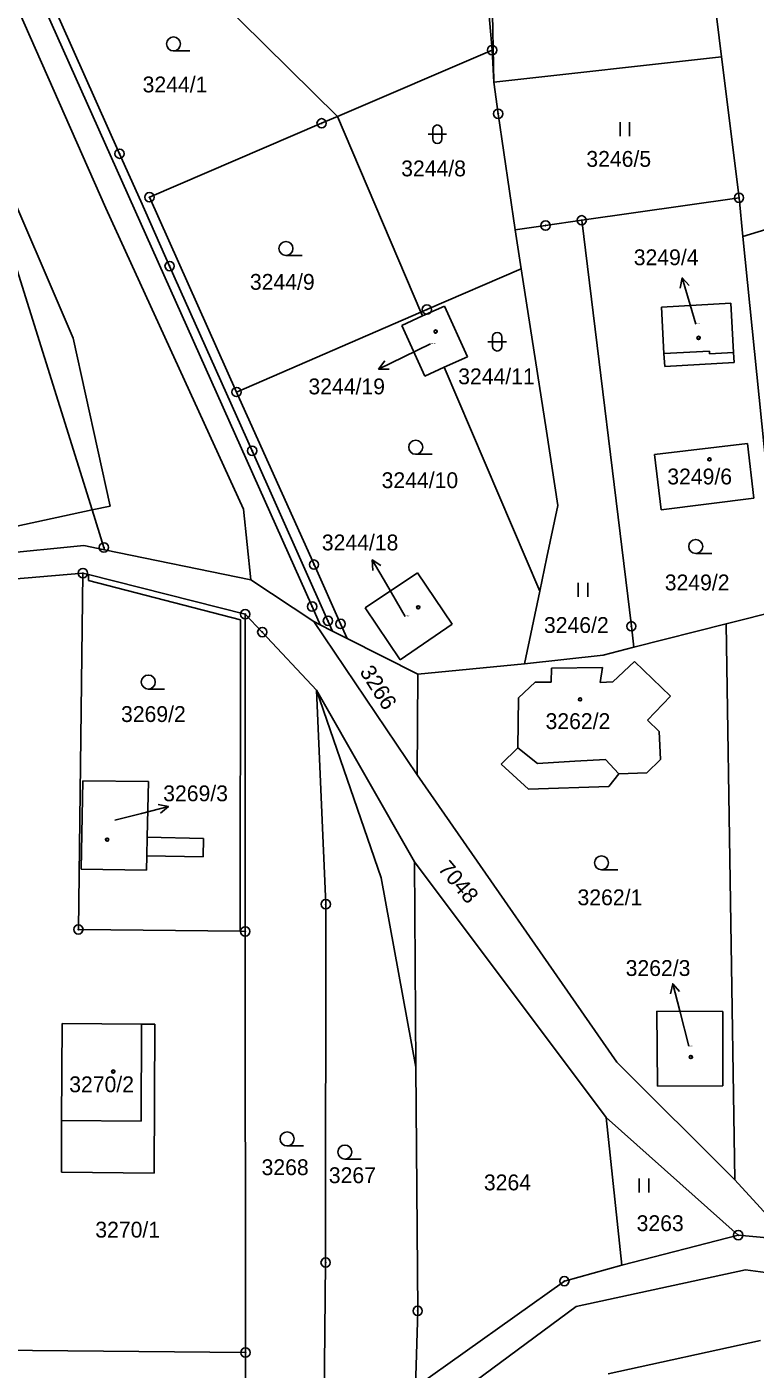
# Model space of a CAD drawing. Extents: x -593183 to -588034, y -1130415 to -1124994.
# Drawn here: x -592537.4 to -592459.2, y -1128135.2 to -1127991.1 of the extents above; entities that cross this region are included whole.
import ezdxf

# ---------------------------------------------------------------- set-up
doc = ezdxf.new("R2010")
doc.units = 0
for name, color, linetype in [('Vrstva 1', 7, 'Continuous'), ('Vrstva 16', 7, 'Continuous'), ('Vrstva 18', 7, 'Continuous'), ('Vrstva 19', 7, 'Continuous'), ('Vrstva 24', 7, 'Continuous'), ('Vrstva 25', 7, 'Continuous'), ('Vrstva 4', 7, 'Continuous')]:
    doc.layers.add(name, color=color, linetype=linetype)

msp = doc.modelspace()

# ---------------------------------------------------------------- linework, layer by layer
at = {"layer": 'Vrstva 1'}
for p, q in [((-592487.85, -1127966.57), (-592487.23, -1127997.07)), ((-592529.53, -1127975.52), (-592504.02, -1128000.74)), ((-592543.23, -1127978.11), (-592528.89, -1128010.56)), ((-592464.13, -1127983.42), (-592462.78, -1127994.34)), ((-592536.01, -1127987.86), (-592506.75, -1128053.34)), ((-592535.34, -1127986.99), (-592527.42, -1128004.73)), ((-592504.02, -1128000.74), (-592487.42, -1127993.61)), ((-592487.42, -1127993.61), (-592487.23, -1127997.07)), ((-592487.23, -1127997.07), (-592462.78, -1127994.34)), ((-592462.78, -1127994.34), (-592460.91, -1128009.46)), ((-592487.23, -1127997.07), (-592486.77, -1128000.44)), ((-592505.72, -1128001.47), (-592504.02, -1128000.74)), ((-592504.02, -1128000.74), (-592495.07, -1128021.74)), ((-592486.77, -1128000.44), (-592484.94, -1128012.91)), ((-592524.21, -1128009.41), (-592505.72, -1128001.47)), ((-592527.42, -1128004.73), (-592525.15, -1128009.81)), ((-592542, -1128005.81), (-592530.36, -1128042.97)), ((-592525.15, -1128009.81), (-592522.04, -1128016.79)), ((-592524.21, -1128009.41), (-592514.85, -1128030.31)), ((-592460.91, -1128009.46), (-592477.8, -1128011.88)), ((-592460.91, -1128009.46), (-592460.49, -1128013.61)), ((-592460.49, -1128013.61), (-592447.19, -1128009.56)), ((-592528.89, -1128010.56), (-592514.12, -1128042.89)), ((-592484.94, -1128012.91), (-592481.68, -1128012.44)), ((-592477.8, -1128011.88), (-592481.68, -1128012.44)), ((-592477.8, -1128011.88), (-592472.47, -1128055.46)), ((-592484.94, -1128012.91), (-592484.29, -1128017.08)), ((-592460.49, -1128013.61), (-592456.72, -1128050.99)), ((-592522.04, -1128016.79), (-592513.18, -1128036.62)), ((-592494.42, -1128021.46), (-592484.29, -1128017.08)), ((-592484.29, -1128017.08), (-592481.59, -1128034.52)), ((-592495.07, -1128021.74), (-592494.42, -1128021.46)), ((-592494.89, -1128022.15), (-592492.54, -1128021.08)), ((-592492.54, -1128021.08), (-592490.06, -1128026.52)), ((-592469.24, -1128021.2), (-592461.78, -1128020.79)), ((-592468.97, -1128026.18), (-592469.24, -1128021.2)), ((-592461.78, -1128020.79), (-592461.49, -1128026.07)), ((-592514.85, -1128030.31), (-592495.07, -1128021.74)), ((-592497.12, -1128023.17), (-592494.89, -1128022.15)), ((-592494.89, -1128022.15), (-592495.07, -1128021.74)), ((-592497.12, -1128023.17), (-592494.64, -1128028.61)), ((-592490.06, -1128026.52), (-592492.55, -1128027.66)), ((-592468.89, -1128027.57), (-592468.97, -1128026.18)), ((-592461.43, -1128027.16), (-592468.89, -1128027.57)), ((-592461.49, -1128026.07), (-592461.43, -1128027.16)), ((-592494.64, -1128028.61), (-592492.55, -1128027.66)), ((-592492.55, -1128027.66), (-592482.3, -1128051.69)), ((-592514.85, -1128030.31), (-592506.54, -1128048.84)), ((-592481.59, -1128034.52), (-592480.36, -1128042.49)), ((-592460.01, -1128035.84), (-592469.98, -1128037.03)), ((-592459.33, -1128041.72), (-592460.01, -1128035.84)), ((-592513.18, -1128036.62), (-592505.04, -1128054.86)), ((-592469.98, -1128037.03), (-592469.28, -1128042.94)), ((-592530.36, -1128042.97), (-592529.1, -1128046.99)), ((-592513.31, -1128050.47), (-592514.12, -1128042.89)), ((-592480.36, -1128042.49), (-592481.54, -1128048.05)), ((-592469.28, -1128042.94), (-592459.33, -1128041.72)), ((-592543.51, -1128048), (-592531.26, -1128046.8)), ((-592531.26, -1128046.8), (-592529.02, -1128047.26)), ((-592529.1, -1128046.99), (-592529.02, -1128047.26)), ((-592529.02, -1128047.26), (-592513.31, -1128050.47)), ((-592506.54, -1128048.84), (-592503.69, -1128055.2)), ((-592481.54, -1128048.05), (-592482.3, -1128051.69)), ((-592543.15, -1128050.75), (-592531.35, -1128049.75)), ((-592531.35, -1128049.75), (-592531.84, -1128088)), ((-592531.35, -1128049.75), (-592530.74, -1128049.9)), ((-592530.74, -1128049.9), (-592513.93, -1128054.16)), ((-592501.03, -1128053.49), (-592495.42, -1128049.71)), ((-592495.42, -1128049.71), (-592491.69, -1128055.24)), ((-592513.31, -1128050.47), (-592506.57, -1128054.94)), ((-592483.95, -1128059.48), (-592482.3, -1128051.69)), ((-592513.93, -1128054.16), (-592512.09, -1128056.08)), ((-592513.93, -1128054.16), (-592513.92, -1128088.21)), ((-592506.75, -1128053.34), (-592505.87, -1128055.3)), ((-592497.29, -1128059.06), (-592501.03, -1128053.49)), ((-592462.3, -1128055.18), (-592456.44, -1128053.72)), ((-592512.09, -1128056.08), (-592506.27, -1128062.3)), ((-592505.87, -1128055.3), (-592506.57, -1128054.94)), ((-592506.57, -1128054.94), (-592495.45, -1128071.4)), ((-592504.54, -1128055.97), (-592505.87, -1128055.3)), ((-592505.04, -1128054.86), (-592504.54, -1128055.97)), ((-592502.99, -1128056.76), (-592504.54, -1128055.97)), ((-592503.69, -1128055.2), (-592502.99, -1128056.76)), ((-592491.69, -1128055.24), (-592497.29, -1128059.06)), ((-592472.47, -1128055.46), (-592472.2, -1128057.7)), ((-592472.2, -1128057.7), (-592462.3, -1128055.18)), ((-592462.3, -1128055.18), (-592461.37, -1128114.86)), ((-592502.99, -1128056.76), (-592495.41, -1128060.61)), ((-592483.95, -1128059.48), (-592475.48, -1128058.54)), ((-592475.48, -1128058.54), (-592472.2, -1128057.7)), ((-592495.41, -1128060.61), (-592483.95, -1128059.48)), ((-592481.03, -1128059.97), (-592481.06, -1128061.44)), ((-592475.55, -1128059.89), (-592481.03, -1128059.97)), ((-592475.83, -1128061.49), (-592475.55, -1128059.89)), ((-592472.12, -1128059.23), (-592474.45, -1128061.41)), ((-592468.28, -1128062.97), (-592472.12, -1128059.23)), ((-592495.41, -1128060.61), (-592495.45, -1128071.4)), ((-592482.8, -1128061.45), (-592484.58, -1128063.15)), ((-592481.06, -1128061.44), (-592482.8, -1128061.45)), ((-592474.45, -1128061.41), (-592475.83, -1128061.49)), ((-592506.27, -1128062.3), (-592505.28, -1128085.29)), ((-592506.27, -1128062.3), (-592495.76, -1128080.73)), ((-592484.58, -1128063.15), (-592484.66, -1128068.5)), ((-592470.72, -1128065.52), (-592468.28, -1128062.97)), ((-592469.47, -1128066.75), (-592470.72, -1128065.52)), ((-592469.34, -1128069.74), (-592469.47, -1128066.75)), ((-592484.66, -1128068.5), (-592486.43, -1128070.26)), ((-592486.43, -1128070.26), (-592483.51, -1128072.94)), ((-592470.8, -1128071.2), (-592469.34, -1128069.74)), ((-592495.45, -1128071.4), (-592474.03, -1128102.24)), ((-592474.87, -1128072.66), (-592473.8, -1128071.29)), ((-592473.8, -1128071.29), (-592470.8, -1128071.2)), ((-592531.36, -1128072.04), (-592531.54, -1128081.52)), ((-592531.36, -1128072.04), (-592524.32, -1128072.1)), ((-592524.32, -1128072.1), (-592524.45, -1128078.11)), ((-592483.51, -1128072.94), (-592474.87, -1128072.66)), ((-592524.45, -1128078.11), (-592518.4, -1128078.24)), ((-592518.4, -1128078.24), (-592518.44, -1128080.21)), ((-592524.53, -1128081.64), (-592524.5, -1128080.08)), ((-592518.44, -1128080.21), (-592524.5, -1128080.08)), ((-592531.54, -1128081.52), (-592524.53, -1128081.64)), ((-592495.76, -1128080.73), (-592495.6, -1128102.77)), ((-592495.76, -1128080.73), (-592475.19, -1128108.18)), ((-592505.28, -1128085.29), (-592505.29, -1128123.75)), ((-592531.84, -1128088), (-592514.46, -1128088.2)), ((-592514.46, -1128088.2), (-592513.92, -1128088.21)), ((-592513.92, -1128088.21), (-592513.9, -1128133.42)), ((-592469.72, -1128096.78), (-592462.66, -1128096.82)), ((-592469.66, -1128104.82), (-592469.72, -1128096.78)), ((-592462.66, -1128096.82), (-592462.63, -1128104.77)), ((-592533.65, -1128108.52), (-592533.59, -1128098.1)), ((-592525.07, -1128098.15), (-592533.59, -1128098.1)), ((-592523.62, -1128098.16), (-592525.07, -1128098.15)), ((-592523.62, -1128098.16), (-592523.7, -1128114.15)), ((-592495.6, -1128102.77), (-592495.41, -1128128.94)), ((-592474.03, -1128102.24), (-592461.37, -1128114.86)), ((-592462.63, -1128104.77), (-592469.66, -1128104.82)), ((-592533.65, -1128114.06), (-592533.65, -1128108.52)), ((-592460.99, -1128120.81), (-592475.19, -1128108.18)), ((-592475.19, -1128108.18), (-592473.48, -1128124.05)), ((-592523.7, -1128114.15), (-592533.65, -1128114.06)), ((-592461.37, -1128114.86), (-592455.46, -1128121.34)), ((-592473.48, -1128124.05), (-592460.99, -1128120.81)), ((-592460.99, -1128120.81), (-592455.46, -1128121.34)), ((-592505.29, -1128123.75), (-592505.61, -1128151.43)), ((-592479.66, -1128125.75), (-592473.48, -1128124.05)), ((-592495.65, -1128137.14), (-592479.66, -1128125.75)), ((-592495.65, -1128137.14), (-592495.41, -1128128.94)), ((-592543.95, -1128133.13), (-592513.9, -1128133.42)), ((-592513.9, -1128133.42), (-592513.89, -1128164.22))]:
    msp.add_line(p, q, dxfattribs=at)
at = {"layer": 'Vrstva 16'}
for p, q in [((-592465.56, -1128023.02), (-592466.17, -1128020.95)), ((-592494.02, -1128025.14), (-592496.9, -1128026.54)), ((-592496.75, -1128054.39), (-592498.77, -1128050.93)), ((-592527.91, -1128076.28), (-592525.07, -1128075.55)), ((-592466.3, -1128100.53), (-592467.28, -1128096.73))]:
    msp.add_line(p, q, dxfattribs=at)
at = {"layer": 'Vrstva 24'}
for centre, radius in [((-592487.42, -1127993.61), 0.5), ((-592487.42, -1127993.61), 0.0327), ((-592505.72, -1128001.47), 0.5), ((-592486.77, -1128000.44), 0.5), ((-592486.77, -1128000.44), 0.0327), ((-592505.72, -1128001.47), 0.0327), ((-592527.42, -1128004.73), 0.5), ((-592527.42, -1128004.73), 0.0327), ((-592524.21, -1128009.41), 0.5), ((-592524.21, -1128009.41), 0.0327), ((-592460.91, -1128009.46), 0.5), ((-592460.91, -1128009.46), 0.0327), ((-592477.8, -1128011.88), 0.5), ((-592481.68, -1128012.44), 0.5), ((-592481.68, -1128012.44), 0.0327), ((-592477.8, -1128011.88), 0.0327), ((-592522.04, -1128016.79), 0.5), ((-592522.04, -1128016.79), 0.0327), ((-592494.42, -1128021.46), 0.5), ((-592494.42, -1128021.46), 0.0327), ((-592514.85, -1128030.31), 0.5), ((-592514.85, -1128030.31), 0.0327), ((-592513.18, -1128036.62), 0.5), ((-592513.18, -1128036.62), 0.0327), ((-592529.1, -1128046.99), 0.5), ((-592529.1, -1128046.99), 0.0327), ((-592506.54, -1128048.84), 0.5), ((-592506.54, -1128048.84), 0.0327), ((-592531.35, -1128049.75), 0.5), ((-592531.35, -1128049.75), 0.0327), ((-592506.75, -1128053.34), 0.5), ((-592513.93, -1128054.16), 0.5), ((-592513.93, -1128054.16), 0.0327), ((-592506.75, -1128053.34), 0.0327), ((-592505.04, -1128054.86), 0.5), ((-592512.09, -1128056.08), 0.5), ((-592512.09, -1128056.08), 0.0327), ((-592505.04, -1128054.86), 0.0327), ((-592503.69, -1128055.2), 0.5), ((-592503.69, -1128055.2), 0.0327), ((-592472.47, -1128055.46), 0.5), ((-592472.47, -1128055.46), 0.0327), ((-592505.28, -1128085.29), 0.5), ((-592505.28, -1128085.29), 0.0327), ((-592531.84, -1128088), 0.5), ((-592513.92, -1128088.21), 0.5), ((-592531.84, -1128088), 0.0327), ((-592513.92, -1128088.21), 0.0327), ((-592460.99, -1128120.81), 0.5), ((-592460.99, -1128120.81), 0.0327), ((-592505.29, -1128123.75), 0.5), ((-592505.29, -1128123.75), 0.0327), ((-592479.66, -1128125.75), 0.5), ((-592479.66, -1128125.75), 0.0327), ((-592495.41, -1128128.94), 0.5), ((-592495.41, -1128128.94), 0.0327), ((-592513.9, -1128133.42), 0.5), ((-592513.9, -1128133.42), 0.0327)]:
    msp.add_circle(centre, radius, dxfattribs=at)
at = {"layer": 'Vrstva 25'}
for p, q in [((-592519.88, -1127993.7), (-592521.63, -1127993.7)), ((-592494.3, -1128002.65), (-592492.3, -1128002.65)), ((-592493.8, -1128003.15), (-592493.8, -1128002.15)), ((-592492.8, -1128002.15), (-592492.8, -1128003.15)), ((-592473.68, -1128001.36), (-592473.68, -1128002.86)), ((-592472.66, -1128002.86), (-592472.66, -1128001.36)), ((-592507.8, -1128015.65), (-592509.55, -1128015.65)), ((-592466.17, -1128020.95), (-592467.01, -1128018.07)), ((-592487.87, -1128024.91), (-592485.87, -1128024.91)), ((-592487.37, -1128025.41), (-592487.37, -1128024.41)), ((-592486.37, -1128024.41), (-592486.37, -1128025.41)), ((-592496.9, -1128026.54), (-592499.6, -1128027.85)), ((-592493.87, -1128036.99), (-592495.62, -1128036.99)), ((-592498.77, -1128050.93), (-592500.29, -1128048.34)), ((-592463.81, -1128047.64), (-592465.56, -1128047.64)), ((-592478.17, -1128050.79), (-592478.17, -1128052.29)), ((-592477.15, -1128052.29), (-592477.15, -1128050.79)), ((-592522.58, -1128062.19), (-592524.33, -1128062.19)), ((-592525.07, -1128075.55), (-592522.17, -1128074.8)), ((-592473.92, -1128081.6), (-592475.67, -1128081.6)), ((-592467.28, -1128096.73), (-592468.03, -1128093.83)), ((-592507.68, -1128111.23), (-592509.43, -1128111.23)), ((-592501.48, -1128112.64), (-592503.23, -1128112.64)), ((-592471.63, -1128114.72), (-592471.63, -1128116.22)), ((-592470.6, -1128116.22), (-592470.6, -1128114.72))]:
    msp.add_line(p, q, dxfattribs=at)
for points in [[(-592467.21, -1128019.17), (-592467.01, -1128018.07), (-592466.25, -1128018.89)], [(-592498.48, -1128027.86), (-592499.6, -1128027.85), (-592498.92, -1128026.96)], [(-592500.21, -1128049.46), (-592500.29, -1128048.34), (-592499.35, -1128048.95)], [(-592523.26, -1128074.57), (-592522.17, -1128074.8), (-592523.01, -1128075.53)], [(-592468.26, -1128094.92), (-592468.03, -1128093.83), (-592467.3, -1128094.67)]]:
    msp.add_lwpolyline(points, dxfattribs=at)
for centre, radius in [((-592521.63, -1127992.95), 0.75), ((-592509.55, -1128014.9), 0.75), ((-592493.48, -1128023.82), 0.175), ((-592493.48, -1128023.82), 0.15), ((-592465.25, -1128024.5), 0.175), ((-592465.25, -1128024.5), 0.15), ((-592495.62, -1128036.24), 0.75), ((-592464.09, -1128037.54), 0.175), ((-592464.09, -1128037.54), 0.15), ((-592465.56, -1128046.89), 0.75), ((-592495.35, -1128053.42), 0.175), ((-592495.35, -1128053.42), 0.15), ((-592524.33, -1128061.44), 0.75), ((-592477.98, -1128063.3), 0.175), ((-592477.98, -1128063.3), 0.15), ((-592528.75, -1128078.36), 0.175), ((-592528.75, -1128078.36), 0.15), ((-592475.67, -1128080.85), 0.75), ((-592466.08, -1128101.69), 0.175), ((-592466.08, -1128101.69), 0.15), ((-592528.1, -1128103.25), 0.175), ((-592528.1, -1128103.25), 0.15), ((-592509.43, -1128110.48), 0.75), ((-592503.23, -1128111.89), 0.75)]:
    msp.add_circle(centre, radius, dxfattribs=at)
for centre, start, end in [((-592493.3, -1128002.15), 90, 180), ((-592493.3, -1128002.15), 0, 90), ((-592493.3, -1128003.15), 180, 270), ((-592493.3, -1128003.15), 270, 0), ((-592486.87, -1128024.41), 90, 180), ((-592486.87, -1128024.41), 0, 90), ((-592486.87, -1128025.41), 180, 270), ((-592486.87, -1128025.41), 270, 0)]:
    msp.add_arc(centre, 0.5, start, end, dxfattribs=at)
at = {"layer": 'Vrstva 4'}
for p, q in [((-592489.65, -1127967.44), (-592487.42, -1127993.61)), ((-592540.63, -1128005.39), (-592532.39, -1128024.52)), ((-592532.39, -1128024.52), (-592528.43, -1128042.55)), ((-592468.97, -1128026.18), (-592464.09, -1128025.92)), ((-592464.09, -1128025.92), (-592464.07, -1128026.22)), ((-592464.07, -1128026.22), (-592461.49, -1128026.07)), ((-592543.11, -1128045.73), (-592530.36, -1128042.97)), ((-592530.36, -1128042.97), (-592528.43, -1128042.55)), ((-592530.74, -1128049.9), (-592530.75, -1128050.55)), ((-592530.75, -1128050.55), (-592514.45, -1128054.77)), ((-592514.45, -1128054.77), (-592514.46, -1128088.2)), ((-592506.27, -1128062.3), (-592499.33, -1128082.44)), ((-592484.66, -1128068.5), (-592482.53, -1128070.17)), ((-592482.53, -1128070.17), (-592478.53, -1128069.95)), ((-592478.53, -1128069.95), (-592475.26, -1128069.77)), ((-592475.26, -1128069.77), (-592473.8, -1128071.29)), ((-592524.45, -1128078.11), (-592524.5, -1128080.08)), ((-592499.33, -1128082.44), (-592495.6, -1128102.77)), ((-592525.11, -1128108.57), (-592525.07, -1128098.15)), ((-592525.11, -1128108.57), (-592533.65, -1128108.52)), ((-592478.38, -1128128.46), (-592460.2, -1128124.52)), ((-592460.2, -1128124.52), (-592436, -1128127.84)), ((-592493.89, -1128139.9), (-592478.38, -1128128.46)), ((-592474.96, -1128135.68), (-592458.59, -1128132.13))]:
    msp.add_line(p, q, dxfattribs=at)

# ---------------------------------------------------------------- texts
at = {"layer": 'Vrstva 16'}
for s, p in [('3249/4', (-592472.21, -1128016.7)), ('3244/19', (-592507.14, -1128030.56)), ('3244/18', (-592505.7, -1128047.31)), ('3269/3', (-592522.73, -1128074.24)), ('3262/3', (-592473.08, -1128092.99))]:
    msp.add_text(s, height=1.7, dxfattribs=at).set_placement(p)
at = {"layer": 'Vrstva 18'}
for s, p in [('3244/1', (-592524.94, -1127998.15)), ('3244/8', (-592497.18, -1128007.16)), ('3246/5', (-592477.3, -1128006.14)), ('3244/9', (-592513.42, -1128019.34)), ('3244/11', (-592491.06, -1128029.48)), ('3244/10', (-592499.28, -1128040.63)), ('3249/2', (-592468.88, -1128051.6)), ('3246/2', (-592481.85, -1128056.17)), ('3269/2', (-592527.26, -1128065.73)), ('3262/1', (-592478.25, -1128085.4)), ('3268', (-592512.17, -1128114.37)), ('3267', (-592504.95, -1128115.23)), ('3264', (-592488.3, -1128116)), ('3270/1', (-592530.02, -1128121.07)), ('3263', (-592471.9, -1128120.38))]:
    msp.add_text(s, height=1.7, dxfattribs=at).set_placement(p)
for s, rotation, p in [('3266', 302.4712, (-592501.7, -1128060.33)), ('7048', 310.4139, (-592493.31, -1128081.52))]:
    msp.add_text(s, height=1.7, rotation=rotation, dxfattribs=at).set_placement(p)
at = {"layer": 'Vrstva 19'}
for s, height, p in [('3249/4', 0.1, (-592465.56, -1128023.02)), ('3244/19', 0.1, (-592494.02, -1128025.14)), ('3249/6', 1.7, (-592468.61, -1128040.23)), ('3244/18', 0.1, (-592496.75, -1128054.39)), ('3262/2', 1.7, (-592481.68, -1128066.49)), ('3269/3', 0.1, (-592527.91, -1128076.28)), ('3262/3', 0.1, (-592466.3, -1128100.53)), ('3270/2', 1.7, (-592532.82, -1128105.47))]:
    msp.add_text(s, height=height, dxfattribs=at).set_placement(p)

doc.saveas('drawing.dxf')
